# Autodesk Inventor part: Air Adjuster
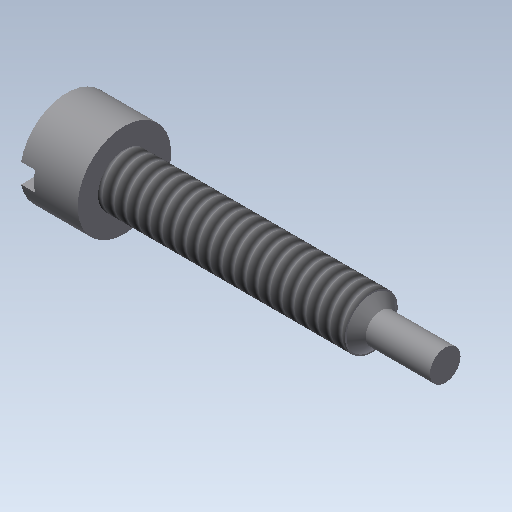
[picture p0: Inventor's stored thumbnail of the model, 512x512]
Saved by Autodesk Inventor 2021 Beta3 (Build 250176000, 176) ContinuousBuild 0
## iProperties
Created: 2012-08
Part Number: Air Adjuster
Material: Generic
Document SubType Name: Modeling
Designer: John
Density: 1 g/cm^3
Appearance: Default
Author: John
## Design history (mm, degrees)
sketch "Sketch1"
  geometry: C1 r 2.477 at (0, 0); 1 further point
  constraints: 1 centre point, 1 coincident
  dimensions: "d1" = 4.953 diameter of C1
extrude "Extrusion1" new body sketch "Sketch1" distance "d3" = 3.048; taper "d4" = 0 deg
sketch "Sketch2"
  geometry: C1 r 2.476 at (0, 0) reference; C2 r 1.397 at (0, 0)
  constraints: 1 centre point, 1 coincident
  dimensions: "d5" = 2.794 diameter of C2
extrude "Extrusion2" join sketch "Sketch2" distance "d6" = 13.081; taper "d7" = 0 deg
sketch "Sketch3"
  geometry: C1 r 1.397 at (0, 0) reference; C2 r 0.813 at (0, 0)
  constraints: 1 centre point, 1 coincident
  dimensions: "d8" = 1.6256 diameter of C2
extrude "Extrusion3" join sketch "Sketch3" distance "d9" = 3.9116; taper "d10" = 0 deg
chamfer "Chamfer1" distance "d11" = 0.508; stored, may be unused: second distance "d12" = 3.175, angle "d13" = 45 deg
thread "Thread1" dims "d14" = 25.4, "d15" = 0
sketch "Sketch4"
  geometry: L1 (-2.476, 0.521)-(2.476, 0.521); L2 (2.476, 0.521)-(2.476, -0.521); L3 (2.476, -0.521)-(-2.476, -0.521); L4 (-2.476, -0.521)-(-2.476, 0.521); C1 r 2.476 at (0, 0) reference
  constraints: 8 end point, 2 parallel, 2 tangent, 1 horizontal, 1 perpendicular
  dimensions: "d16" = 1.0414 distance of L1.end L2.end; "d18" = 0.5207 distance from line of C1.centre L3 (= 0.5 x d16)
extrude "Extrusion4" cut sketch "Sketch4" distance "d19" = 0.7366; taper "d20" = 0 deg
body "Solid1"
